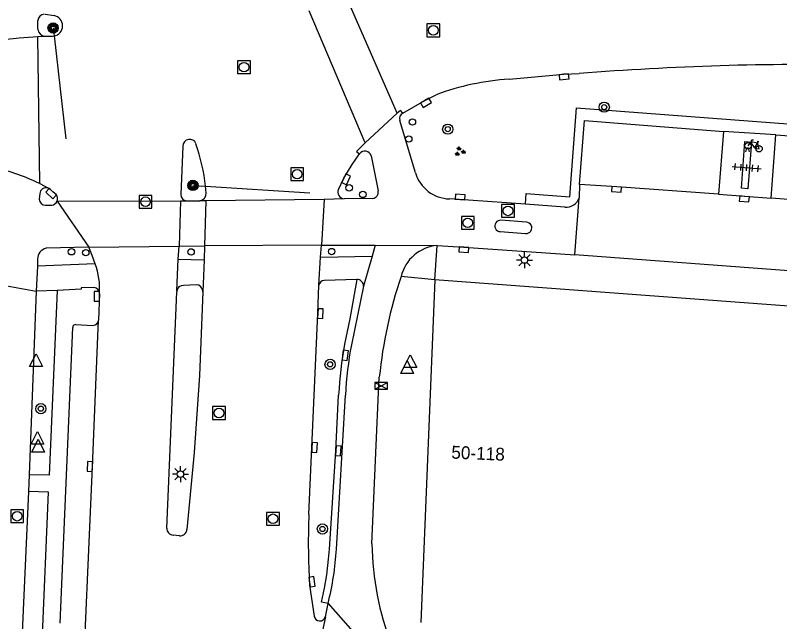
# Model space of a CAD drawing. Extents: x 132999 to 136000, y 398499 to 400501.
# Drawn here: x 133982.2 to 134041.7, y 398651 to 398698.2 of the extents above; entities that cross this region are included whole.
import ezdxf

# ---------------------------------------------------------------- set-up
doc = ezdxf.new("R2010")
doc.units = 0
for name, color, linetype in [('gg-anno-huisnummerreeks BGT', 7, 'Continuous'), ('gg-bbg-hoofdgebouw', 7, 'Continuous'), ('gg-knt-verharding', 7, 'Continuous'), ('gg-knt-verharding nz', 7, 'Continuous'), ('gt-grn-groengrens', 7, 'Continuous'), ('gt-grn-weggrens', 7, 'Continuous'), ('gt-knt-lijn portaal', 7, 'Continuous'), ('gt-symb-boom', 7, 'Continuous'), ('gt-symb-drukknoppaal', 7, 'Continuous'), ('gt-symb-fietsenrek', 7, 'Continuous'), ('gt-symb-groenvak', 7, 'Continuous'), ('gt-symb-kolk', 7, 'Continuous'), ('gt-symb-lichtmast', 7, 'Continuous'), ('gt-symb-portaalmast', 7, 'Continuous'), ('gt-symb-rioolschacht', 7, 'Continuous'), ('gt-symb-tegel verharding', 7, 'Continuous'), ('gt-symb-verkeersbordpaal', 7, 'Continuous'), ('gt-symb-verkeersregelinstallatiekast', 7, 'Continuous'), ('gt-symb-verkeersregelinstallatiepaal', 7, 'Continuous'), ('gt-symb-waterafsluiter', 7, 'Continuous')]:
    doc.layers.add(name, color=color, linetype=linetype)

# ---------------------------------------------------------------- blocks, each defined once
blk = doc.blocks.new('gt0-RS')
at = {"layer": 'gt-symb-rioolschacht'}
blk.add_lwpolyline([(-0.5, -0.5), (0.5, -0.5), (0.5, 0.5), (-0.5, 0.5)], close=True, dxfattribs=at)
blk.add_circle((0, 0), 0.375, dxfattribs=at)
blk = doc.blocks.new('gt0-LMAST')
at = {"layer": 'gt-symb-lichtmast'}
for p, q in [((-0.005, 0.246), (-0.005, 0.621)), ((-0.182, 0.173), (-0.447, 0.438)), ((0.172, 0.173), (0.437, 0.438)), ((-0.255, -0.004), (-0.63, -0.004)), ((-0.182, -0.181), (-0.447, -0.446)), ((-0.005, -0.254), (-0.005, -0.629)), ((0.437, -0.446), (0.172, -0.181)), ((0.245, -0.004), (0.62, -0.004))]:
    blk.add_line(p, q, dxfattribs=at)
blk.add_circle((-0.005, -0.004), 0.25, dxfattribs=at)
blk = doc.blocks.new('gt0-KOLK')
at = {"layer": 'gt-symb-kolk'}
blk.add_lwpolyline([(0, 0), (0.375, 0), (0.375, 0.4), (-0.375, 0.4), (-0.375, 0), (0, 0)], dxfattribs=at)
blk = doc.blocks.new('gt0-VPAAL')
at = {"layer": 'gt-symb-verkeersbordpaal'}
blk.add_circle((0, 0), 0.25, dxfattribs=at)
blk = doc.blocks.new('gt0-BOOM')
at = {"layer": 'gt-symb-boom'}
for radius in [0.4, 0.2]:
    blk.add_circle((0, 0), radius, dxfattribs=at)
blk = doc.blocks.new('gt0-VIPAAL')
at = {"layer": 'gt-symb-verkeersregelinstallatiepaal'}
blk.add_circle((0, 0), 0.25, dxfattribs=at)
blk = doc.blocks.new('gt0-DPAAL')
at = {"layer": 'gt-symb-drukknoppaal'}
blk.add_circle((0, 0), 0.25, dxfattribs=at)
blk = doc.blocks.new('gt0-WAFSL')
at = {"layer": 'gt-symb-waterafsluiter'}
for p, q in [((-0.5, -0.333), (0, 0.667)), ((0, 0.667), (0.5, -0.333)), ((0.5, -0.333), (-0.5, -0.333))]:
    blk.add_line(p, q, dxfattribs=at)
blk = doc.blocks.new('gt0-PORTM')
at = {"layer": 'gt-symb-portaalmast'}
for radius in [0.4, 0.33, 0.27, 0.21, 0.15]:
    blk.add_circle((0, 0), radius, dxfattribs=at)
blk = doc.blocks.new('gt0-TEG1')
at = {"layer": 'gt-symb-tegel verharding'}
for p, q in [((-1.125, 0), (1.125, 0)), ((-0.9, -0.25), (-0.9, 0.25)), ((-0.45, -0.25), (-0.45, 0.25)), ((0, -0.25), (0, 0.25)), ((0.45, -0.25), (0.45, 0.25)), ((0.9, -0.25), (0.9, 0.25))]:
    blk.add_line(p, q, dxfattribs=at)
blk = doc.blocks.new('gt0-FREK')
at = {"layer": 'gt-symb-fietsenrek'}
for p, q in [((0.259, 0.762), (0.294, 0.823)), ((0.54, 0.335), (0.259, 0.762)), ((0.294, 0.823), (0.767, 0.714)), ((0.767, 0.714), (0.54, 0.335)), ((0.757, 0.841), (0.866, 0.816)), ((0.767, 0.714), (0.84, 0.822)), ((0.895, 0.252), (0.767, 0.714))]:
    blk.add_line(p, q, dxfattribs=at)
for points in [[(0.036, 0.476), (0.228, 0.708), (0.259, 0.762)], [(0.294, 0.823), (0.36, 0.937), (0.452, 0.935)], [(-0.124, 0), (-0.047, 0.312), (0.053, 0.312), (0.12, 0)], [(0.54, 0.335), (0.555, 0.305), (0.895, 0.252)]]:
    blk.add_lwpolyline(points, dxfattribs=at)
for centre in [(0.036, 0.476), (0.895, 0.252)]:
    blk.add_circle(centre, 0.252, dxfattribs=at)
blk = doc.blocks.new('gt0-GRVAK')
at = {"layer": 'gt-symb-groenvak'}
for p, q in [((-0.11, 0.189), (-0.228, 0.24)), ((-0.182, 0.153), (0.088, 0.153)), ((-0.091, 0.211), (-0.156, 0.322)), ((-0.047, 0.214), (-0.047, 0.393)), ((-0.004, 0.211), (0.061, 0.322)), ((0.015, 0.189), (0.133, 0.24)), ((0.262, -0.052), (0.197, 0.059)), ((0.305, -0.049), (0.305, 0.13)), ((0.349, -0.052), (0.414, 0.059)), ((-0.245, -0.228), (-0.363, -0.177)), ((-0.318, -0.264), (-0.047, -0.264)), ((-0.226, -0.206), (-0.291, -0.095)), ((-0.183, -0.203), (-0.183, -0.024)), ((-0.139, -0.206), (-0.074, -0.095)), ((-0.12, -0.228), (-0.002, -0.177)), ((0.243, -0.074), (0.125, -0.023)), ((0.17, -0.11), (0.441, -0.11)), ((0.368, -0.074), (0.486, -0.023))]:
    blk.add_line(p, q, dxfattribs=at)
blk = doc.blocks.new('gt0-VRIKST')
at = {"layer": 'gt-symb-verkeersregelinstallatiekast'}
for p, q in [((-0.501, -0.249), (0.501, 0.249)), ((-0.501, 0.249), (0.501, -0.249))]:
    blk.add_line(p, q, dxfattribs=at)
blk.add_lwpolyline([(0.501, 0.249), (-0.501, 0.249), (-0.501, -0.249), (0.501, -0.249)], close=True, dxfattribs=at)

msp = doc.modelspace()

# ---------------------------------------------------------------- linework, layer by layer
at = {"layer": 'gg-bbg-hoofdgebouw'}
for p, q in [((134014.843, 398677.579), (134013.747, 398650.906)), ((134107.734, 398670.637), (134014.843, 398677.579))]:
    msp.add_line(p, q, dxfattribs=at)
at = {"layer": 'gg-knt-verharding'}
for p, q in [((133984.476, 398698.255), (133985.182, 398698.155)), ((133983.9, 398697.093), (133983.913, 398697.763)), ((134013.318, 398685.904), (134012.114, 398689.99)), ((134037.304, 398689.139), (134036.914, 398684.245)), ((134041.393, 398688.859), (134037.304, 398689.139)), ((134041.023, 398683.931), (134041.393, 398688.859)), ((133995.203, 398687.995), (133995.047, 398684.227)), ((134009.879, 398687.233), (134010.419, 398684.509)), ((133985.28, 398684.26), (133984.872, 398684.629)), ((133997.027, 398684.342), (133996.974, 398684.869)), ((134026.11, 398684.992), (134026.075, 398683.976)), ((133984.066, 398684.298), (133984.008, 398683.857)), ((134010.001, 398683.924), (134007.757, 398683.882)), ((134021.883, 398683.46), (134015.972, 398683.877)), ((134025.731, 398679.522), (134026.075, 398683.976)), ((134036.914, 398684.245), (134041.023, 398683.931)), ((133984.517, 398683.386), (133984.998, 398683.389)), ((133995.487, 398683.735), (133996.527, 398683.735)), ((134024.966, 398683.243), (134021.883, 398683.46)), ((134021.97, 398682.077), (134019.983, 398682.216)), ((134019.922, 398681.334), (134021.905, 398681.19)), ((133987.88, 398680.131), (133984.554, 398680.044)), ((133994.834, 398679.187), (133994.922, 398680.213)), ((133994.922, 398680.213), (133996.882, 398680.24)), ((133996.882, 398680.24), (133996.858, 398679.148)), ((134005.923, 398679.343), (134006.007, 398680.283)), ((134006.007, 398680.283), (134010.183, 398680.276)), ((134010.183, 398680.276), (134009.947, 398679.422)), ((133983.89, 398679.19), (133983.875, 398678.652)), ((133994.728, 398676.712), (133994.834, 398679.187)), ((133994.834, 398679.187), (133996.858, 398679.148)), ((133996.858, 398679.148), (133996.765, 398676.654)), ((134005.795, 398677.161), (134005.923, 398679.343)), ((134005.923, 398679.343), (134009.947, 398679.422)), ((134009.947, 398679.422), (134009.286, 398677.08)), ((134105.791, 398673.539), (134025.731, 398679.522)), ((133983.875, 398678.652), (133983.792, 398676.71)), ((133988.382, 398678.815), (133983.875, 398678.652)), ((134008.745, 398677.599), (134006.217, 398677.524)), ((133985.415, 398676.758), (133983.792, 398676.71)), ((133996.235, 398677.199), (133995.248, 398677.135)), ((134009.286, 398677.08), (134008.329, 398672.521)), ((133983.792, 398676.71), (133983.23, 398662.404)), ((133988.709, 398676.527), (133988.64, 398674.45)), ((133993.964, 398658.248), (133994.725, 398676.64)), ((133994.728, 398676.712), (133994.725, 398676.64)), ((133985.639, 398650.854), (133986.623, 398673.869)), ((133986.881, 398674.098), (133988.203, 398674.036)), ((134009.924, 398657.022), (134010.507, 398670.005)), ((134007.159, 398656.625), (134007.867, 398668.605)), ((133983.23, 398662.404), (133983.178, 398661.092)), ((133983.178, 398661.092), (133982.546, 398647.02)), ((133994.95, 398657.661), (133994.451, 398657.712)), ((134006.307, 398651.358), (134006.512, 398652.38))]:
    msp.add_line(p, q, dxfattribs=at)
for points in [[(133984.461, 398696.546), (133984.932, 398696.557), (133985.051, 398696.552), (133985.169, 398696.564)], [(134020.617, 398693.199), (134024.875, 398693.583), (134026.064, 398693.639)], [(134012.338, 398690.55), (134014.04, 398691.54), (134014.938, 398691.994)], [(134026.11, 398684.992), (134026.481, 398689.992), (134037.304, 398689.139)], [(134041.393, 398688.859), (134102.595, 398684.352), (134102.259, 398679.336)], [(134007.325, 398684.621), (134007.746, 398685.494), (134008.397, 398686.559), (134008.964, 398687.388)], [(133984.872, 398684.629), (133984.787, 398684.691), (133984.69, 398684.732)], [(133988.382, 398678.815), (133988.148, 398679.479), (133987.88, 398680.131)], [(134015.003, 398680.247), (134017.1, 398680.126), (134025.731, 398679.522)], [(134008.745, 398677.599), (134008.207, 398674.542), (134007.793, 398672.58)], [(133985.415, 398676.758), (133984.787, 398662.378), (133983.23, 398662.404)], [(133988.287, 398676.978), (133987.296, 398676.949), (133987.29, 398676.843), (133985.415, 398676.758)], [(134005.024, 398659.311), (134005.262, 398664.531), (134005.72, 398674.961), (134005.795, 398677.161)], [(133996.765, 398676.654), (133996.505, 398670.121), (133996.097, 398664.127), (133995.526, 398658.153)], [(133987.599, 398650.067), (133988.165, 398663.045), (133988.64, 398674.45)], [(134006.512, 398652.38), (134006.013, 398652.495), (134006.234, 398653.569), (134006.418, 398654.614), (134006.557, 398655.832), (134006.617, 398656.616), (134007.116, 398664.28), (134007.339, 398668.612)], [(133985.948, 398643.82), (133986.258, 398649.228), (133984.253, 398649.314), (133984.75, 398661.046), (133983.178, 398661.092)], [(134005.047, 398654.287), (134005.08, 398653.81), (134005.435, 398651.408)]]:
    msp.add_lwpolyline(points, dxfattribs=at)
for centre, radius, start, end in [((133984.447, 398697.72), 0.536, 95.27305, 175.4314), ((133985.025, 398697.361), 0.81, 280.2117, 78.85199), ((133984.514, 398697.162), 0.618, 186.39689, 265.05094), ((134044.067, 398465.834), 228.515, 88.99329, 94.51862), ((134021.934, 398673.007), 20.235, 93.73198, 110.22731), ((134012.514, 398690.155), 0.432, 113.96444, 202.43274), ((133995.73, 398687.995), 0.527, 20.71163, 179.95738), ((133980.978, 398682.983), 16.107, 6.7243, 18.8274), ((134009.385, 398687.094), 0.513, 15.72169, 145.04917), ((134016.068, 398686.754), 2.878, 197.17046, 268.08777), ((133984.548, 398684.271), 0.482, 72.83107, 176.80715), ((134007.805, 398684.406), 0.526, 155.8059, 264.81297), ((134009.92, 398684.424), 0.507, 279.24358, 9.66253), ((133984.944, 398683.888), 0.501, 337.48581, 47.89429), ((133995.534, 398684.22), 0.487, 179.14133, 264.47177), ((133996.418, 398684.334), 0.609, 280.29639, 0.74546), ((134025.06, 398684.306), 1.067, 264.93459, 341.99129), ((133984.523, 398683.903), 0.517, 185.06058, 269.38054), ((133984.946, 398683.884), 0.498, 275.98048, 337.80413), ((134019.938, 398681.776), 0.442, 84.17715, 267.91018), ((134021.941, 398681.633), 0.445, 265.39545, 86.22218), ((133984.776, 398679.186), 0.886, 104.52381, 179.7448), ((134015.278, 398677.087), 3.172, 94.9724, 166.25036), ((133983.359, 398676.93), 5.365, 355.69491, 20.57231), ((134006.217, 398677.097), 0.427, 90.01133, 171.39222), ((134008.781, 398677.095), 0.506, 358.35142, 94.02656), ((134046.264, 398666.393), 35.939, 161.42621, 174.23251), ((133988.261, 398676.531), 0.448, 359.48696, 86.70785), ((133995.205, 398676.656), 0.481, 84.92212, 173.33194), ((133996.224, 398676.658), 0.541, 359.59422, 88.80693), ((133988.188, 398674.489), 0.454, 271.88212, 355.02157), ((133986.854, 398673.869), 0.231, 83.26765, 179.91667), ((134038.249, 398667.085), 30.948, 169.77323, 177.1725), ((134039.624, 398666.844), 31.806, 169.71757, 176.82541), ((134058.037, 398657.042), 53.062, 177.54882, 182.97578), ((133994.469, 398658.218), 0.506, 176.58999, 267.92546), ((133995.005, 398658.18), 0.522, 263.92768, 357.07802), ((133985.412, 398657.768), 21.777, 345.67604, 356.99192), ((134033.703, 398657.531), 23.784, 181.2266, 200.56341), ((134005.876, 398651.472), 0.446, 188.24871, 345.18786)]:
    msp.add_arc(centre, radius, start, end, dxfattribs=at)
at = {"layer": 'gg-knt-verharding nz'}
for p, q in [((134011.884, 398690.568), (134008.196, 398699.052)), ((134009.412, 398688.24), (134005.036, 398698.527)), ((133983.908, 398696.512), (133984.461, 398696.546)), ((133984.056, 398685.068), (133983.908, 398696.512)), ((134011.884, 398690.568), (134009.412, 398688.24)), ((133984.056, 398685.068), (133984.69, 398684.732)), ((134007.757, 398683.882), (134006.209, 398683.825)), ((133985.407, 398683.696), (133995.032, 398683.733)), ((133985.407, 398683.696), (133987.88, 398680.131)), ((133995.032, 398683.733), (133994.922, 398680.213)), ((133995.032, 398683.733), (133995.487, 398683.735)), ((133997.006, 398683.739), (133996.527, 398683.735)), ((133997.006, 398683.739), (133996.882, 398680.24)), ((134006.209, 398683.825), (133997.006, 398683.739)), ((134006.209, 398683.825), (134006.007, 398680.283)), ((133987.88, 398680.131), (133994.922, 398680.213)), ((134006.007, 398680.283), (133996.882, 398680.24)), ((134006.307, 398651.358), (134004.461, 398642.817))]:
    msp.add_line(p, q, dxfattribs=at)
for points in [[(133980.287, 398696.185), (133982.445, 398696.423), (133983.908, 398696.512)], [(134012.338, 398690.55), (134012.161, 398690.77), (134011.884, 398690.568)], [(134009.412, 398688.24), (134008.739, 398687.573), (134008.964, 398687.388)], [(134039.207, 398684.675), (134038.705, 398684.717), (134038.985, 398688.351), (134039.487, 398688.308), (134039.207, 398684.675)], [(134036.914, 398684.245), (134029, 398684.82), (134026.11, 398684.992)], [(134102.259, 398679.336), (134059.231, 398682.532), (134041.023, 398683.931)]]:
    msp.add_lwpolyline(points, dxfattribs=at)
msp.add_arc((133977.377, 398671.694), 14.949, 63.4608, 77.68146, dxfattribs=at)
at = {"layer": 'gt-grn-groengrens'}
msp.add_line((134021.883, 398683.46), (134021.943, 398684.295), dxfattribs=at)
msp.add_lwpolyline([(134021.943, 398684.295), (134025.35, 398684.038), (134025.871, 398690.959), (134041.278, 398689.798), (134064.782, 398688.028), (134088.285, 398686.258), (134103.546, 398685.18), (134103.159, 398679.698), (134109.042, 398679.102), (134112.393, 398678.536), (134114.969, 398677.94), (134117.963, 398676.942), (134121.628, 398675.457), (134126.055, 398673.321), (134127.057, 398675.397), (134128.419, 398674.74), (134143.491, 398667.47), (134158.563, 398660.199), (134164.803, 398657.189), (134171.043, 398654.178), (134179.068, 398650.308), (134187.092, 398646.437), (134191.745, 398644.192), (134196.399, 398641.947)], dxfattribs=at)
at = {"layer": 'gt-grn-weggrens'}
for p, q in [((134010.183, 398680.276), (134015.003, 398680.247)), ((134014.843, 398677.579), (134015.003, 398680.247)), ((134014.843, 398677.579), (134012.197, 398677.841)), ((133981.213, 398677.156), (133983.792, 398676.71)), ((134006.512, 398652.38), (134009.271, 398649.284))]:
    msp.add_line(p, q, dxfattribs=at)
at = {"layer": 'gt-knt-lijn portaal'}
for p, q in [((133985.099, 398697.187), (133985.169, 398696.564)), ((133985.169, 398696.564), (133986.077, 398688.549)), ((133995.992, 398684.933), (133996.974, 398684.869)), ((133996.974, 398684.869), (134005.102, 398684.342))]:
    msp.add_line(p, q, dxfattribs=at)

# ---------------------------------------------------------------- block references
at = {"layer": 'gt-symb-boom'}
for p in [(134028.025, 398691.024), (134015.835, 398689.312), (134006.671, 398671.002), (133984.144, 398667.551), (134006.077, 398658.184)]:
    msp.add_blockref('gt0-BOOM', p, dxfattribs=at)
at = {"layer": 'gt-symb-drukknoppaal'}
for p in [(134012.799, 398688.544), (134009.221, 398684.228), (133986.529, 398679.765)]:
    msp.add_blockref('gt0-DPAAL', p, dxfattribs=at)
at = {"layer": 'gt-symb-fietsenrek'}
msp.add_blockref('gt0-FREK', (134039.187, 398687.538), dxfattribs=at)
at = {"layer": 'gt-symb-groenvak'}
msp.add_blockref('gt0-GRVAK', (134016.769, 398687.565), dxfattribs=at)
at = {"layer": 'gt-symb-kolk'}
for p, rotation in [((134024.875, 398693.583), -174.84429481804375), ((134014.04, 398691.54), -149.80571392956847), ((134007.746, 398685.494), -115.76381431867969), ((133985.076, 398684.444), 137.91141736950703), ((134029, 398684.82), 175.8694613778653), ((134016.794, 398683.823), -4.070667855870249), ((134038.953, 398684.077), 175.29819168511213), ((134017.1, 398680.126), 176.70557131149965), ((133988.701, 398676.287), 90), ((134005.72, 398674.961), -92.51058532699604), ((134007.651, 398671.723), -97.56744600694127), ((134005.262, 398664.531), -92.6073255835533), ((134007.116, 398664.28), -93.7228190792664), ((133988.165, 398663.045), 87.61069653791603), ((134005.063, 398654.048), -81.9851577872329)]:
    msp.add_blockref('gt0-KOLK', p, dxfattribs=dict(at, rotation=rotation))
at = {"layer": 'gt-symb-lichtmast'}
for p in [(134021.815, 398679.123), (133995.02, 398662.457)]:
    msp.add_blockref('gt0-LMAST', p, dxfattribs=at)
at = {"layer": 'gt-symb-portaalmast'}
for p in [(133985.099, 398697.187), (133995.992, 398684.933)]:
    msp.add_blockref('gt0-PORTM', p, dxfattribs=at)
at = {"layer": 'gt-symb-rioolschacht'}
for p in [(134014.709, 398697.006), (133999.964, 398694.137), (134004.108, 398685.808), (133992.297, 398683.658), (134020.529, 398682.95), (134017.396, 398682.019), (133998.022, 398667.214), (133982.3, 398659.18), (134002.226, 398658.978)]:
    msp.add_blockref('gt0-RS', p, dxfattribs=at)
at = {"layer": 'gt-symb-tegel verharding', "rotation": -4.701808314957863}
msp.add_blockref('gt0-TEG1', (134039.121, 398686.309), dxfattribs=at)
at = {"layer": 'gt-symb-verkeersbordpaal'}
msp.add_blockref('gt0-VPAAL', (133995.845, 398679.751), dxfattribs=at)
at = {"layer": 'gt-symb-verkeersregelinstallatiekast'}
msp.add_blockref('gt0-VRIKST', (134010.655, 398669.329), dxfattribs=at)
at = {"layer": 'gt-symb-verkeersregelinstallatiepaal'}
for p in [(134013.083, 398689.868), (134008.158, 398684.745), (133987.641, 398679.695), (134006.794, 398679.781)]:
    msp.add_blockref('gt0-VIPAAL', p, dxfattribs=at)
at = {"layer": 'gt-symb-waterafsluiter'}
for p in [(133983.768, 398671.164), (134012.918, 398671.078), (134012.679, 398670.621), (133983.886, 398665.111), (133983.937, 398664.501)]:
    msp.add_blockref('gt0-WAFSL', p, dxfattribs=at)

# ---------------------------------------------------------------- texts
at = {"layer": 'gg-anno-huisnummerreeks BGT'}
msp.add_text('50-118', height=1, rotation=357.6, dxfattribs=at).set_placement((134016.099, 398663.669))

doc.saveas('drawing.dxf')
